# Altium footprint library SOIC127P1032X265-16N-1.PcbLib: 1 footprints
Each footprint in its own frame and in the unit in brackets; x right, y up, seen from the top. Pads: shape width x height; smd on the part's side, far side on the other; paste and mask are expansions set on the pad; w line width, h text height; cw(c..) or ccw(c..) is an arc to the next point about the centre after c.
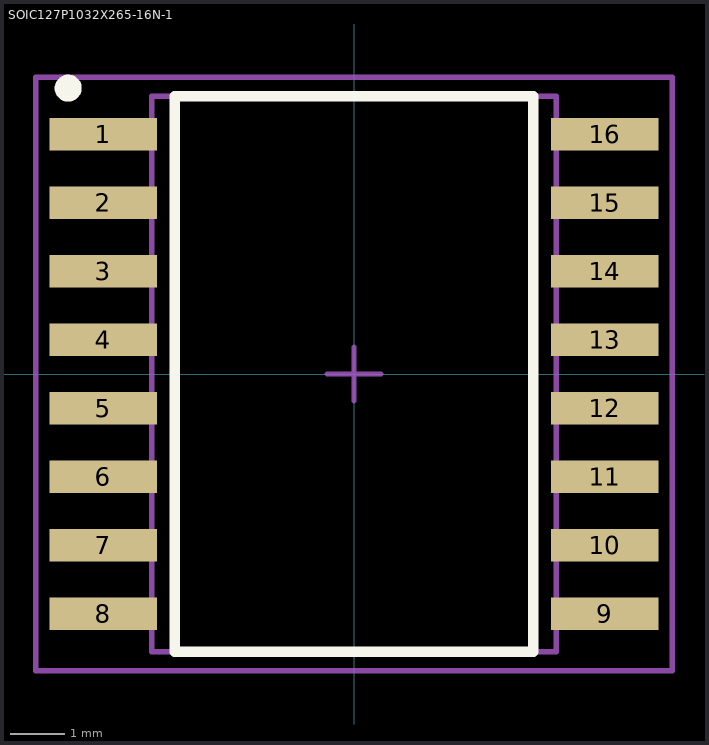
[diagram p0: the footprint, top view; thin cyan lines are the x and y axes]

## SOIC127P1032X265-16N-1 [mm] "SOIC,1.27mm pitch;16 pin,7.50mm W X 10.30mm L X 2.65mm H body"
height 2.65
pads (16):
  rect 2x0.6 smd paste+0 mask+0: 1(-4.65,4.445) 2(-4.65,3.175) 3(-4.65,1.905) 4(-4.65,0.635) 5(-4.65,-0.635) 6(-4.65,-1.905) 7(-4.65,-3.175) 8(-4.65,-4.445) 9(4.65,-4.445) 10(4.65,-3.175) 11(4.65,-1.905) 12(4.65,-0.635) 13(4.65,0.635) 14(4.65,1.905) 15(4.65,3.175) 16(4.65,4.445)
Top Overlay:
  circle w0.25: c-5.3,5.3 r0.125
  lines w0.2: -3.325,-5.15 -3.325,5.15 3.325,5.15 3.325,-5.15 -3.325,-5.15
Mechanical 3:
  text ".DESIGNATOR" at 0,0 h1.2
Mechanical 13:
  lines w0.1: -3.75,-5.15 -3.75,5.15 3.75,5.15 3.75,-5.15 -3.75,-5.15
Mechanical 15:
  lines w0.1: -0.5,0 0.5,0 ; 0,-0.5 0,0.5 ; -5.9,-5.5 -5.9,5.5 5.9,5.5 5.9,-5.5 -5.9,-5.5
3D body: height 0.28, standoff 0, extent 4.391,-4.658 5.162,-4.238
3D body: height 1.3, standoff 1.02, extent 3.75,-4.658 4.327,-4.238
3D body: height 1.3, standoff 0, extent 4.327,-4.658 4.602,-4.238
3D body: height 1.3, standoff 0, extent 4.327,-3.388 4.602,-2.968
3D body: height 1.3, standoff 1.02, extent 3.75,-3.388 4.327,-2.968
3D body: height 0.28, standoff 0, extent 4.391,-3.388 5.162,-2.968
3D body: height 0.28, standoff 0, extent 4.391,-0.848 5.162,-0.428
3D body: height 1.3, standoff 1.02, extent 3.75,-0.848 4.327,-0.428
3D body: height 1.3, standoff 0, extent 4.327,-0.848 4.602,-0.428
3D body: height 1.3, standoff 0, extent 4.327,-2.118 4.602,-1.698
3D body: height 1.3, standoff 1.02, extent 3.75,-2.118 4.327,-1.698
3D body: height 0.28, standoff 0, extent 4.391,-2.118 5.162,-1.698
3D body: height 0.28, standoff 0, extent 4.391,1.692 5.162,2.112
3D body: height 1.3, standoff 1.02, extent 3.75,1.692 4.327,2.112
3D body: height 1.3, standoff 0, extent 4.327,1.692 4.602,2.112
3D body: height 1.3, standoff 0, extent 4.327,0.422 4.602,0.842
3D body: height 1.3, standoff 1.02, extent 3.75,0.422 4.327,0.842
3D body: height 0.28, standoff 0, extent 4.391,0.422 5.162,0.842
3D body: height 0.28, standoff 0, extent 4.391,4.232 5.162,4.652
3D body: height 1.3, standoff 1.02, extent 3.75,4.232 4.327,4.652
3D body: height 1.3, standoff 0, extent 4.327,4.232 4.602,4.652
3D body: height 1.3, standoff 0, extent 4.327,2.962 4.602,3.382
3D body: height 1.3, standoff 1.02, extent 3.75,2.962 4.327,3.382
3D body: height 0.28, standoff 0, extent 4.391,2.962 5.162,3.382
3D body: height 0.28, standoff 0, extent -5.162,-3.388 -4.391,-2.968
3D body: height 1.3, standoff 1.02, extent -4.327,-3.388 -3.75,-2.968
3D body: height 1.3, standoff 0, extent -4.602,-3.388 -4.327,-2.968
3D body: height 1.3, standoff 0, extent -4.602,-4.658 -4.327,-4.238
3D body: height 1.3, standoff 1.02, extent -4.327,-4.658 -3.75,-4.238
3D body: height 0.28, standoff 0, extent -5.162,-4.658 -4.391,-4.238
3D body: height 0.28, standoff 0, extent -5.162,-0.848 -4.391,-0.428
3D body: height 1.3, standoff 1.02, extent -4.327,-0.848 -3.75,-0.428
3D body: height 1.3, standoff 0, extent -4.602,-0.848 -4.327,-0.428
3D body: height 1.3, standoff 0, extent -4.602,-2.118 -4.327,-1.698
3D body: height 1.3, standoff 1.02, extent -4.327,-2.118 -3.75,-1.698
3D body: height 0.28, standoff 0, extent -5.162,-2.118 -4.391,-1.698
3D body: height 0.28, standoff 0, extent -5.162,1.692 -4.391,2.112
3D body: height 1.3, standoff 1.02, extent -4.327,1.692 -3.75,2.112
3D body: height 1.3, standoff 0, extent -4.602,1.692 -4.327,2.112
3D body: height 1.3, standoff 0, extent -4.602,0.422 -4.327,0.842
3D body: height 1.3, standoff 1.02, extent -4.327,0.422 -3.75,0.842
3D body: height 0.28, standoff 0, extent -5.162,0.422 -4.391,0.842
3D body: height 0.28, standoff 0, extent -5.162,2.962 -4.391,3.382
3D body: height 1.3, standoff 1.02, extent -4.327,2.962 -3.75,3.382
3D body: height 1.3, standoff 0, extent -4.602,2.962 -4.327,3.382
3D body: height 1.3, standoff 0, extent -4.602,4.232 -4.327,4.652
3D body: height 1.3, standoff 1.02, extent -4.327,4.232 -3.75,4.652
3D body: height 0.28, standoff 0, extent -5.162,4.232 -4.391,4.652
3D body: height 2.65, standoff 0.1, extent -3.75,-5.15 3.75,5.15
3D body: height 2.65, standoff 2.65, extent -3.22,4.15 -2.62,4.75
